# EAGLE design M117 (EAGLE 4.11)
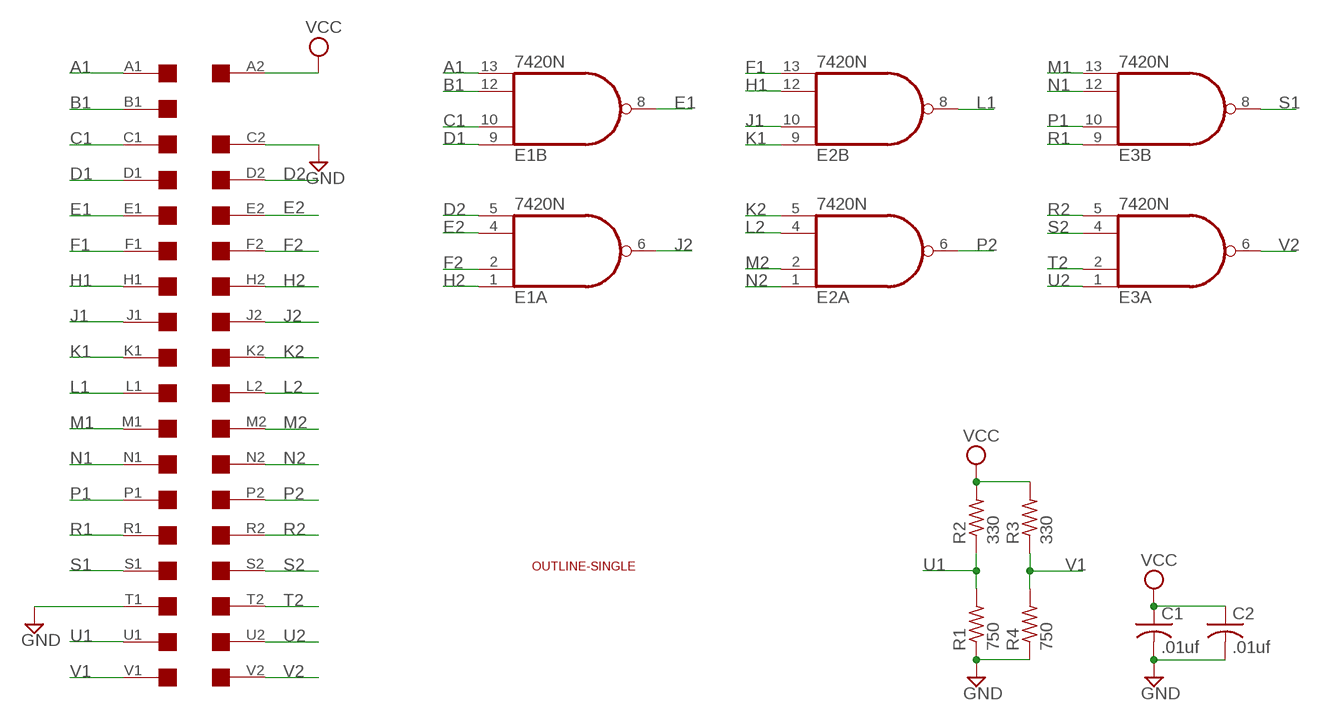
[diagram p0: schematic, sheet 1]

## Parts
C1  .01uf  C-US050-025X075  [C050-025X075]
C2  .01uf  C-US050-025X075  [C050-025X075]
E1  7420N  74S20N  [DIL14]
E2  7420N  74S20N  [DIL14]
E3  7420N  74S20N  [DIL14]
R1  750  R-US_0207/10  [0207/10]
R2  330  R-US_0207/10  [0207/10]
R3  330  R-US_0207/10  [0207/10]
R4  750  R-US_0207/10  [0207/10]
U$1  SINGLE  [EDGE-CON2]
U$4  OUTLINE-SINGLE  [SINGLE]

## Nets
A1: E1.13(B:I3) U$1.A1
B1: E1.12(B:I2) U$1.B1
C1: E1.10(B:I1) U$1.C1
D1: E1.9(B:I0) U$1.D1
D2: E1.5(A:I3) U$1.D2
E1: E1.8(B:O) U$1.E1
E2: E1.4(A:I2) U$1.E2
F1: E2.13(B:I3) U$1.F1
F2: E1.2(A:I1) U$1.F2
GND: C1.2 C2.2 R1.1 R4.1 U$1.C2 U$1.T1
H1: E2.12(B:I2) U$1.H1
H2: E1.1(A:I0) U$1.H2
J1: E2.10(B:I1) U$1.J1
J2: E1.6(A:O) U$1.J2
K1: E2.9(B:I0) U$1.K1
K2: E2.5(A:I3) U$1.K2
L1: E2.8(B:O) U$1.L1
L2: E2.4(A:I2) U$1.L2
M1: E3.13(B:I3) U$1.M1
M2: E2.2(A:I1) U$1.M2
N1: E3.12(B:I2) U$1.N1
N2: E2.1(A:I0) U$1.N2
P1: E3.10(B:I1) U$1.P1
P2: E2.6(A:O) U$1.P2
R1: E3.9(B:I0) U$1.R1
R2: E3.5(A:I3) U$1.R2
S1: E3.8(B:O) U$1.S1
S2: E3.4(A:I2) U$1.S2
T2: E3.2(A:I1) U$1.T2
U1: R1.2 R2.1 U$1.U1
U2: E3.1(A:I0) U$1.U2
V1: R3.1 R4.2 U$1.V1
V2: E3.6(A:O) U$1.V2
VCC: C1.1 C2.1 R2.2 R3.2 U$1.A2
Unconnected: U$1.B2

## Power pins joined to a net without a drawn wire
GND: E1.7(P:GND) E2.7(P:GND) E3.7(P:GND)
VCC: E1.14(P:VCC) E2.14(P:VCC) E3.14(P:VCC)

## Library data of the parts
C1 C2 = rcl:C-US: CAPACITOR, American symbol
E1-E3 = 74xx-us:74*20: Dual 4-input NAND gate
R1-R4 = rcl:R-US_: RESISTOR, American symbol
U$1 = dec-con:SINGLE: Single-Height DEC board
U$4 = dec-con:OUTLINE-*: Board outlines for DEC boards.

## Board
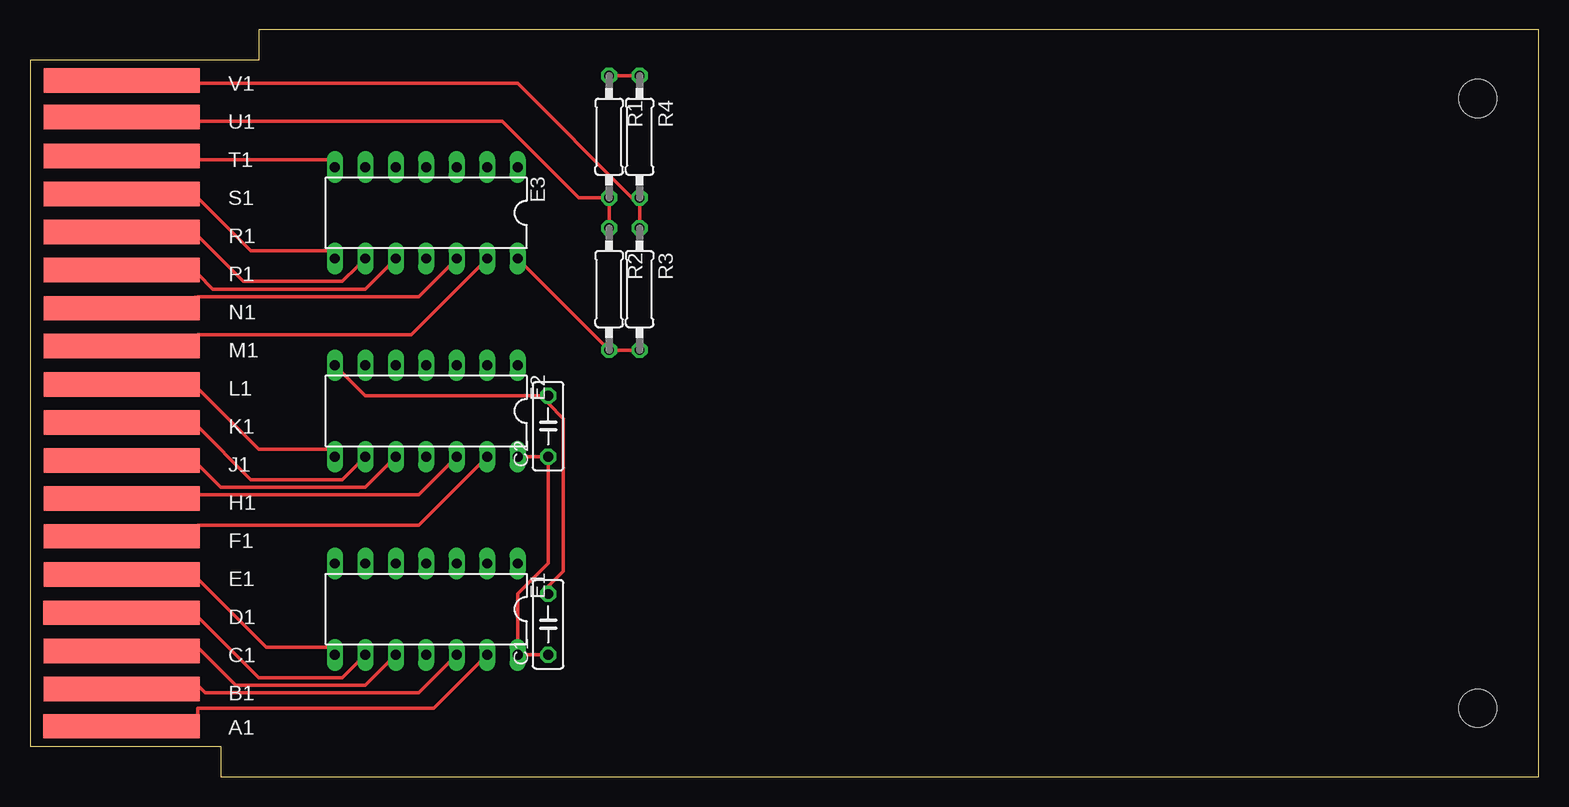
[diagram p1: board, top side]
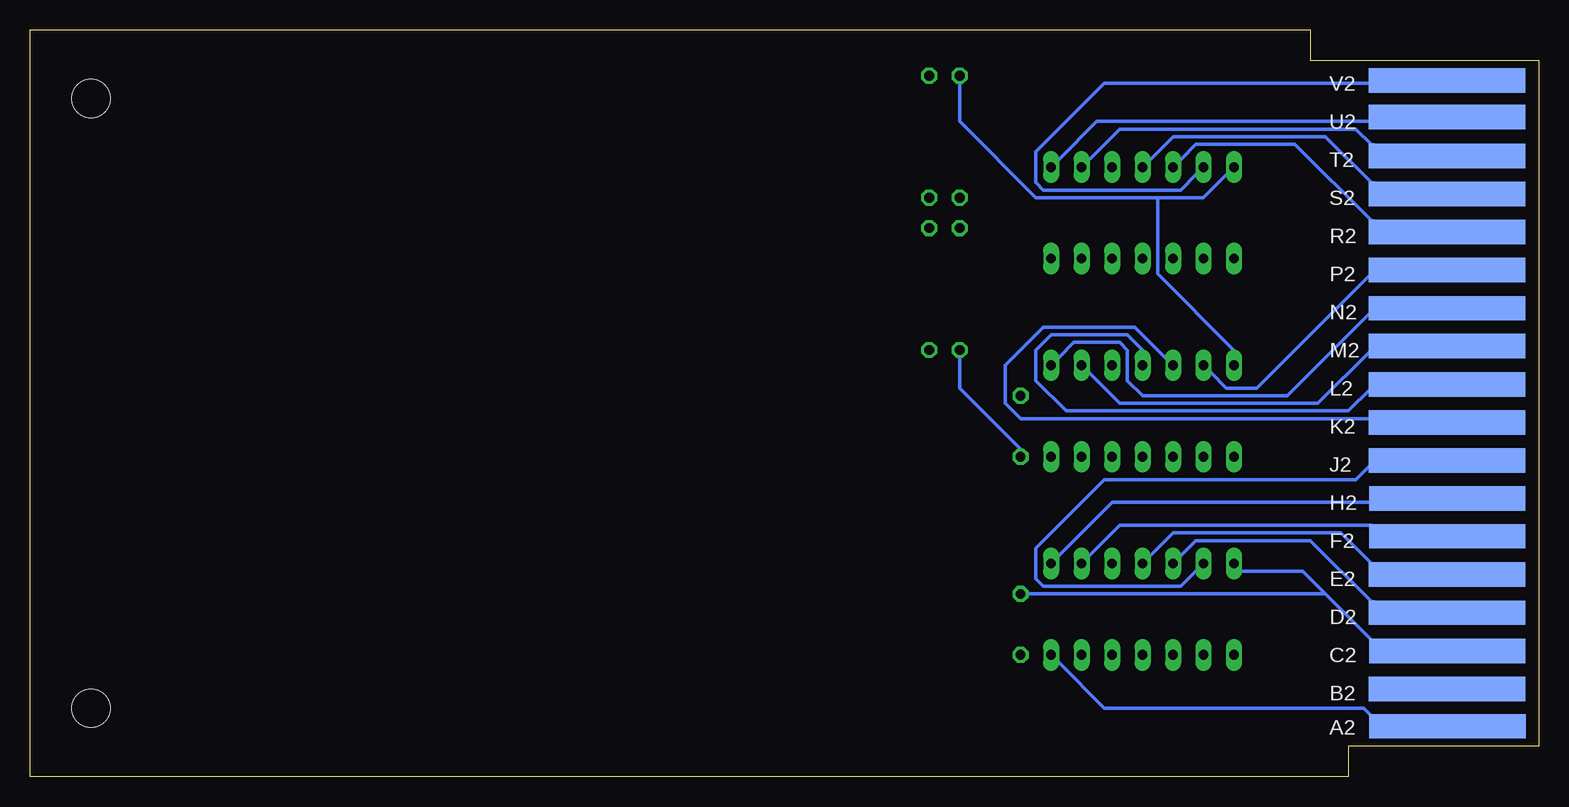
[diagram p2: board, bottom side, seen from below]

Size 125.73 x 62.23 mm. Coordinates in mm from the lower left corner, seen from the top.
Copper layers (1*16): Top 0.035mm / dielectric 1.5mm / Bottom 0.035mm
Design rules "10mils": minimum track width 12mil, minimum drill 28mil, track to track 10mil, track to pad 10mil, pad to pad 10mil, via to via 10mil, smd to smd 10mil, copper to edge 25mil, drill to drill 10mil, minimum pad ring 10mil, minimum via ring 8mil, stop-mask expansion 0mil, vias tented up to drill 0mil, thermal gap 10mil

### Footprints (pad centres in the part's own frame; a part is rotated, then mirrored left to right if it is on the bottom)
C050-025X075 = drill 0.813 octagon: 1 -2.54,0; 2 2.54,0
DIL14 = drill 0.813 long: 1 -7.62,-3.81; 2 -5.08,-3.81; 3 -2.54,-3.81; 4 0,-3.81; 5 2.54,-3.81; 6 5.08,-3.81; 7 7.62,-3.81; 8 7.62,3.81; 9 5.08,3.81; 10 2.54,3.81; 11 0,3.81; 12 -2.54,3.81; 13 -5.08,3.81; 14 -7.62,3.81
0207/10 = drill 0.813 octagon: 1 -5.08,0; 2 5.08,0
EDGE-CON2 = smd 13.017 x 2.032: A1 7.633,4.207; B1 7.639,7.327; C1 7.636,10.489; D1 7.633,13.665; E1 7.642,16.84; F1 7.642,20.041; H1 7.642,23.19; J1 7.642,26.34; K1 7.642,29.515; L1 7.642,32.69; M1 7.642,35.89; N1 7.642,39.04; P1 7.642,42.24; R1 7.642,45.39; S1 7.642,48.565; T1 7.642,51.74; U1 7.642,54.966; V1 7.642,58.026 | smd 13.017 x 2.032 bottom: A2 7.614,4.207; B2 7.642,7.328; C2 7.617,10.49; D2 7.642,13.665; E2 7.642,16.84; F2 7.617,20.041; H2 7.617,23.19; J2 7.642,26.34; K2 7.642,29.515; L2 7.642,32.69; M2 7.642,35.89; N2 7.642,39.04; P2 7.642,42.24; R2 7.642,45.39; S2 7.642,48.565; T2 7.642,51.74; U2 7.642,54.966; V2 7.642,58.026
SINGLE = hole 3.175: 120.65,56.515; 120.65,5.715

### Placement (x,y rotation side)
C1  43.18,12.7 90 top
C2  43.18,29.21 90 top
E1  33.02,13.97 180 top
E2  33.02,30.48 180 top
E3  33.02,46.99 180 top
R1  48.26,53.34 270 top
R2  48.26,40.64 270 top
R3  50.8,40.64 270 top
R4  50.8,53.34 270 top
U$1  0,0 0 top
U$4  0,0 0 top

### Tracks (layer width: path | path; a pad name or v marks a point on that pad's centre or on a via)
A1
  Top 0.305: E1.13 37.47,9.53 33.66,5.71 13.97,5.71 13.97,5.08 U$1.A1
B1
  Top 0.305: E1.12 34.93,9.53 32.39,6.99 14.61,6.99 13.97,7.62 U$1.B1
C1
  Top 0.305: E1.10 29.85,9.53 27.94,7.62 17.15,7.62 13.97,10.79 U$1.C1
D1
  Top 0.305: E1.9 27.31,9.53 26.04,8.26 19.05,8.26 13.97,13.34 U$1.D1
D2
  Bottom 0.305: E1.5 29.85,18.41 28.58,19.68 19.05,19.68 13.97,14.61 U$1.D2
E1
  Top 0.305: E1.8 24.77,10.79 19.69,10.79 13.97,16.51 U$1.E1
E2
  Bottom 0.305: E1.4 32.39,18.41 30.48,20.32 16.51,20.32 13.97,17.78 U$1.E2
F1
  Top 0.305: E2.13 37.47,26.04 32.39,20.95 13.97,20.95 U$1.F1
F2
  Bottom 0.305: E1.2 37.47,18.41 34.93,20.95 13.97,20.95 U$1.F2
GND
  Top 0.305: E2.7 26.04,33.66 27.94,31.75 42.55,31.75 C2.2 43.18,31.11 44.45,29.84 44.45,17.14 43.18,15.88 C1.2 | R1.1 48.9,58.42 50.17,58.42 R4.1 | E3.7 24.77,51.44 13.97,51.44 U$1.T1
  Bottom 0.305: 17.78,15.24 13.97,11.43 U$1.C2 | 17.78,15.24 19.69,17.14 24.77,17.14 E1.7 | 17.78,15.24 42.55,15.24 C1.2 | 31.75,48.26 27.94,48.26 26.04,50.16 E3.7 | 31.75,48.26 41.91,48.26 48.26,54.61 48.26,57.78 R1.1 | 31.75,48.26 31.75,41.91 25.4,35.56 E2.7
H1
  Top 0.305: E2.12 34.93,26.04 32.39,23.5 13.97,23.5 U$1.H1
H2
  Bottom 0.305: E1.1 40.01,18.41 35.56,22.86 13.97,22.86 U$1.H2
J1
  Top 0.305: E2.10 29.85,26.04 27.94,24.13 15.88,24.13 13.97,26.04 U$1.J1
J2
  Bottom 0.305: E1.6 28.58,17.14 29.85,15.88 41.28,15.88 41.91,16.51 41.91,19.05 36.2,24.77 15.24,24.77 13.97,26.04 U$1.J2
K1
  Top 0.305: E2.9 27.31,26.04 26.04,24.77 18.42,24.77 13.97,29.21 U$1.K1
K2
  Bottom 0.305: E2.5 31.12,34.92 33.66,37.47 41.28,37.47 44.45,34.29 44.45,31.11 43.18,29.84 13.97,29.84 U$1.K2
L1
  Top 0.305: E2.8 24.77,27.3 19.05,27.3 13.97,32.38 U$1.L1
L2
  Bottom 0.305: E2.4 33.02,35.56 34.29,36.83 40.64,36.83 41.91,35.56 41.91,33.02 39.37,30.48 15.88,30.48 13.97,32.38 U$1.L2
M1
  Top 0.305: E3.13 37.47,42.55 31.75,36.83 13.97,36.83 U$1.M1
M2
  Bottom 0.305: E2.2 37.47,33.66 34.93,31.11 18.42,31.11 13.97,35.56 U$1.M2
N1
  Top 0.305: E3.12 34.93,42.55 32.39,40.01 13.97,40.01 U$1.N1
N2
  Bottom 0.305: E2.1 40.01,34.92 38.74,36.2 34.93,36.2 34.29,35.56 34.29,33.02 33.02,31.75 20.96,31.75 13.97,38.73 U$1.N2
P1
  Top 0.305: E3.10 29.85,42.55 27.94,40.64 15.24,40.64 13.97,41.91 U$1.P1
P2
  Bottom 0.305: E2.6 27.31,33.66 26.04,32.38 23.5,32.38 13.97,41.91 U$1.P2
R1
  Top 0.305: E3.9 27.31,42.55 26.04,41.27 17.78,41.27 13.97,45.09 U$1.R1
R2
  Bottom 0.305: E3.5 29.85,51.44 28.58,52.7 20.32,52.7 13.97,46.35 U$1.R2
S1
  Top 0.305: E3.8 24.77,43.81 18.42,43.81 13.97,48.26 U$1.S1
S2
  Bottom 0.305: E3.4 32.39,51.44 30.48,53.34 17.78,53.34 13.97,49.53 U$1.S2
T2
  Bottom 0.305: E3.2 37.47,51.44 34.93,53.98 15.24,53.98 13.97,52.7 U$1.T2
U1
  Top 0.305: R2.1 48.26,46.35 48.26,47.62 R1.2 47.63,48.26 45.72,48.26 39.37,54.61 13.97,54.61 U$1.U1
U2
  Bottom 0.305: E3.1 40.01,51.44 36.83,54.61 13.97,54.61 U$1.U2
V1
  Top 0.305: R3.1 50.8,46.35 50.8,47.62 R4.2 50.17,48.26 40.64,57.78 13.97,57.78 U$1.V1
V2
  Bottom 0.305: E3.6 28.58,50.16 29.85,48.9 41.28,48.9 41.91,49.53 41.91,52.07 36.2,57.78 13.97,57.78 U$1.V2
VCC
  Top 0.305: R3.2 50.17,35.56 48.9,35.56 R2.2 41.28,42.55 E3.14 | C1.1 42.55,10.16 41.28,10.16 E1.14 40.64,11.43 40.64,15.24 43.18,17.78 43.18,26.04 C2.1 42.55,26.67 41.28,26.67 E2.14
  Bottom 0.305: R2.2 48.26,34.92 48.26,32.38 43.18,27.3 C2.1 | E1.14 40.01,9.53 36.2,5.71 14.61,5.71 13.97,5.08 U$1.A2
